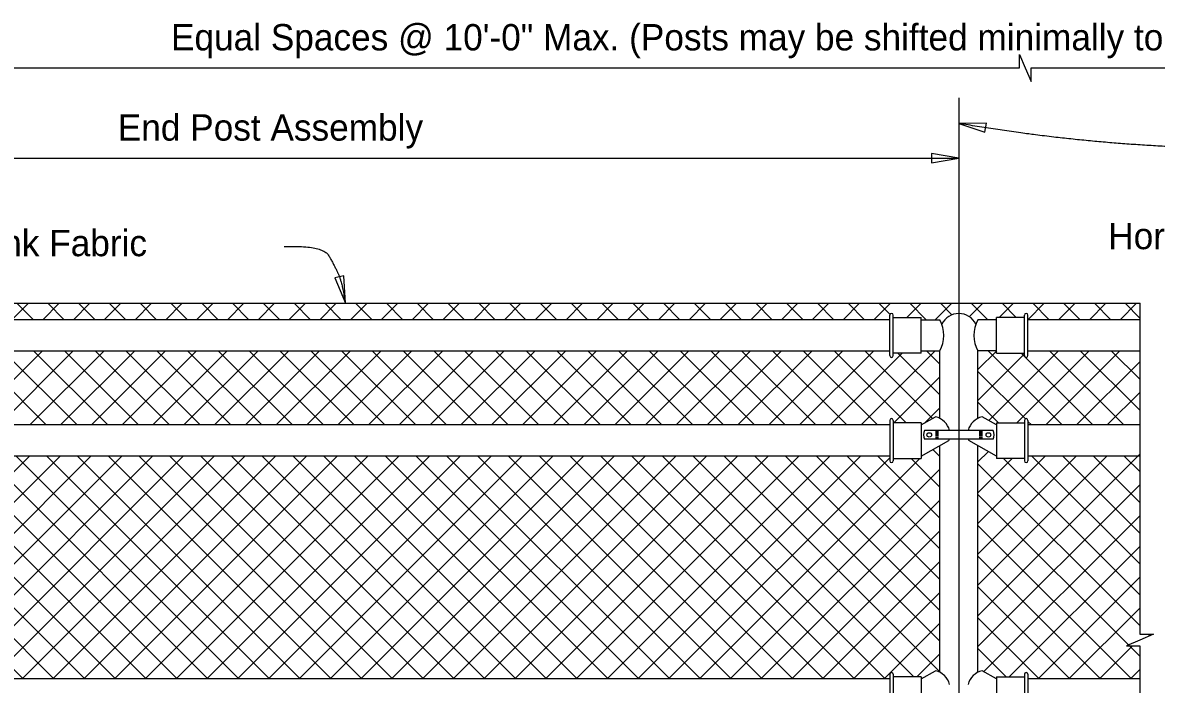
# Model space of a CAD drawing. Extents: x 110341.7 to 110413.5, y 110387.3 to 110417.8.
# Drawn here: x 110348.41 to 110357.09, y 110410.5 to 110415.57 of the extents above; entities that cross this region are included whole.
import ezdxf

# ---------------------------------------------------------------- set-up
doc = ezdxf.new("R2010")
doc.units = 0
for name, color, linetype in [('AdhocPoint_dp', 7, 'Continuous'), ('Border', 7, 'Continuous'), ('CL_Major', 7, 'Continuous'), ('Patterning', 7, 'Continuous'), ('SheetBorder_dp', 7, 'Continuous')]:
    doc.layers.add(name, color=color, linetype=linetype)

msp = doc.modelspace()

# ---------------------------------------------------------------- linework, layer by layer
at = {"layer": 'AdhocPoint_dp'}
for p, q in [((110355.0484, 110413.022), (110355.0484, 110413.3316)), ((110355.0753, 110413.022), (110355.0753, 110413.3316)), ((110355.0753, 110413.3138), (110355.2882, 110413.3138)), ((110355.2882, 110413.0415), (110355.2882, 110413.3138)), ((110355.2882, 110413.0415), (110355.2882, 110413.3138)), ((110355.8673, 110413.0415), (110355.8673, 110413.3138)), ((110356.0803, 110413.3138), (110355.8673, 110413.3138)), ((110356.0803, 110413.022), (110356.0803, 110413.3316)), ((110356.1071, 110413.022), (110356.1071, 110413.3316)), ((110355.0484, 110413.2966), (110346.1071, 110413.2966)), ((110355.2882, 110413.2957), (110355.4319, 110413.2957)), ((110355.8674, 110413.2957), (110355.7237, 110413.2957)), ((110356.9647, 110413.2966), (110356.1071, 110413.2966)), ((110355.0484, 110413.057), (110346.1071, 110413.057)), ((110355.2882, 110413.0415), (110355.0753, 110413.0415)), ((110355.2882, 110413.058), (110355.4319, 110413.058)), ((110355.432, 110412.5414), (110355.432, 110413.058)), ((110355.7237, 110412.5414), (110355.7237, 110413.058)), ((110355.8674, 110413.058), (110355.7237, 110413.058)), ((110355.8673, 110413.0415), (110356.0803, 110413.0415)), ((110356.9647, 110413.057), (110356.1071, 110413.057)), ((110355.0484, 110412.5261), (110355.0484, 110412.2165)), ((110355.0753, 110412.5261), (110355.0753, 110412.2165)), ((110355.2882, 110412.4919), (110355.3991, 110412.5532)), ((110355.8673, 110412.4919), (110355.7565, 110412.5532)), ((110356.0803, 110412.5261), (110356.0803, 110412.2165)), ((110356.1071, 110412.5261), (110356.1071, 110412.2165)), ((110355.0484, 110412.4912), (110346.1071, 110412.4912)), ((110355.2882, 110412.5066), (110355.0753, 110412.5066)), ((110355.2882, 110412.5066), (110355.2882, 110412.2344)), ((110355.8402, 110412.4493), (110355.3154, 110412.4493)), ((110355.3978, 110412.4415), (110355.4212, 110412.4415)), ((110355.3978, 110412.4319), (110355.4212, 110412.4319)), ((110355.7578, 110412.4415), (110355.7343, 110412.4415)), ((110355.7578, 110412.4319), (110355.7343, 110412.4319)), ((110355.8673, 110412.5066), (110355.8673, 110412.2344)), ((110355.8673, 110412.5066), (110356.0803, 110412.5066)), ((110356.9647, 110412.4912), (110356.1071, 110412.4912)), ((110355.2882, 110412.2525), (110355.5022, 110412.371)), ((110355.8402, 110412.3815), (110355.3154, 110412.3815)), ((110355.3978, 110412.421), (110355.4212, 110412.421)), ((110355.3978, 110412.4093), (110355.4212, 110412.4093)), ((110355.3978, 110412.3975), (110355.4212, 110412.3975)), ((110355.3978, 110412.3877), (110355.4212, 110412.3877)), ((110355.8673, 110412.2525), (110355.6534, 110412.371)), ((110355.7578, 110412.421), (110355.7343, 110412.421)), ((110355.7578, 110412.4093), (110355.7343, 110412.4093)), ((110355.7578, 110412.3975), (110355.7343, 110412.3975)), ((110355.7578, 110412.3877), (110355.7343, 110412.3877)), ((110355.432, 110410.5968), (110355.432, 110412.3322)), ((110355.7237, 110410.5969), (110355.7237, 110412.3321)), ((110355.0484, 110412.2516), (110346.1071, 110412.2516)), ((110355.0753, 110412.2344), (110355.2882, 110412.2344)), ((110356.0803, 110412.2344), (110355.8673, 110412.2344)), ((110356.9647, 110412.2516), (110356.1071, 110412.2516)), ((110355.2882, 110410.5473), (110355.3991, 110410.6087)), ((110355.8673, 110410.5473), (110355.7565, 110410.6087)), ((110355.0484, 110410.5466), (110346.1071, 110410.5466)), ((110355.0484, 110410.5816), (110355.0484, 110410.272)), ((110355.0753, 110410.5816), (110355.0753, 110410.272)), ((110355.2882, 110410.5621), (110355.0753, 110410.5621)), ((110355.2882, 110410.5621), (110355.2882, 110410.2898)), ((110355.8673, 110410.5621), (110355.8673, 110410.2898)), ((110355.8673, 110410.5621), (110356.0803, 110410.5621)), ((110356.0803, 110410.5816), (110356.0803, 110410.272)), ((110356.1071, 110410.5816), (110356.1071, 110410.272)), ((110356.9647, 110410.5466), (110356.1071, 110410.5466))]:
    msp.add_line(p, q, dxfattribs=at)
for centre, radius, start, end in [((110355.062, 110413.332), 0.0134, 0, 180), ((110355.5778, 110413.1987), 0.1459, 26.24953, 153.75047), ((110356.0936, 110413.332), 0.0134, 0, 180), ((110355.2183, 110413.1768), 0.2445, 330.92084, 29.07916), ((110355.9373, 110413.1768), 0.2445, 150.92084, 209.07916), ((110355.062, 110413.0222), 0.0134, 180, 0), ((110356.0936, 110413.0222), 0.0134, 180, 0), ((110355.062, 110412.5261), 0.0134, 0, 180), ((110356.0936, 110412.5261), 0.0134, 0, 180), ((110355.062, 110412.2163), 0.0134, 180, 0), ((110356.0936, 110412.2163), 0.0134, 180, 0), ((110355.062, 110410.5815), 0.0134, 0, 180), ((110356.0936, 110410.5815), 0.0134, 0, 180)]:
    msp.add_arc(centre, radius, start, end, dxfattribs=at)
for centre, major_axis, start_param, end_param in [((110355.3646, 110412.4173), (0.146, 0), 0.231126, 1.331255), ((110355.791, 110412.4173), (-0.146, 0), 4.95193, 6.05206), ((110355.3846, 110412.4153), (-0.0776, 0), 5.810211, 6.75616), ((110355.771, 110412.4153), (0.0776, 0), 5.810211, 6.75616), ((110355.3646, 110412.4173), (0.146, 0), 5.947976, 6.024627), ((110355.791, 110412.4173), (-0.146, 0), 0.258558, 0.335209), ((110355.3646, 110410.4727), (0.146, 0), 0.231126, 1.331255), ((110355.791, 110410.4727), (-0.146, 0), 4.95193, 6.05206)]:
    msp.add_ellipse(centre, major_axis=major_axis, ratio=0.957868, start_param=start_param, end_param=end_param, dxfattribs=at)
for centre, major_axis in [((110355.3512, 110412.4148), (0.0178, 0)), ((110355.8044, 110412.4148), (-0.0178, 0))]:
    msp.add_ellipse(centre, major_axis=major_axis, ratio=0.957868, dxfattribs=at)
at = {"layer": 'Border'}
for p, q in [((110343.2819, 110415.2246), (110354.5778, 110415.2246)), ((110345.5778, 110414.5336), (110355.5778, 110414.5336))]:
    msp.add_line(p, q, dxfattribs=at)
for points in [[(110354.5778, 110415.2246), (110356.0414, 110415.2246), (110356.0414, 110415.3279), (110356.0864, 110415.2246), (110356.1314, 110415.1213), (110356.1314, 110415.2246), (110367.5259, 110415.2246)], [(110356.9647, 110413.4227), (110356.9647, 110410.8892), (110357.0681, 110410.8892), (110356.9647, 110410.8442), (110356.8614, 110410.7992), (110356.9647, 110410.7992), (110356.9647, 110410.307)]]:
    msp.add_lwpolyline(points, dxfattribs=at)
for points in [[(110355.5778, 110414.8004), (110355.7778, 110414.7325), (110355.789, 110414.8021)], [(110355.5778, 110414.5336), (110355.3695, 110414.5689), (110355.3695, 110414.4983)], [(110350.8806, 110413.4227), (110350.8677, 110413.6335), (110350.799, 110413.6175)]]:
    msp.add_lwpolyline(points, close=True, dxfattribs=at)
for points in [[(110359.5594, 110414.6017), (110358.756, 110414.6017), (110357.3667, 110414.6017), (110356.1853, 110414.6963), (110355.5778, 110414.8004)], [(110350.4116, 110413.8578), (110350.709, 110413.867), (110350.7987, 110413.7074), (110350.8546, 110413.5877), (110350.8807, 110413.4227)]]:
    msp.add_open_spline(points, degree=2, dxfattribs=at)
at = {"layer": 'CL_Major'}
msp.add_line((110355.5778, 110414.9959), (110355.5778, 110405.5769), dxfattribs=at)
at = {"layer": 'Patterning'}
for p, q in [((110345.5778, 110413.4227), (110356.9648, 110413.4227)), ((110348.3275, 110413.2966), (110348.4536, 110413.4227)), ((110348.3663, 110413.4227), (110348.4924, 110413.2966)), ((110348.5632, 110413.2966), (110348.6893, 110413.4227)), ((110348.602, 110413.4227), (110348.7281, 110413.2966)), ((110348.7989, 110413.2966), (110348.925, 110413.4227)), ((110348.8377, 110413.4227), (110348.9638, 110413.2966)), ((110349.0346, 110413.2966), (110349.1607, 110413.4227)), ((110349.0734, 110413.4227), (110349.1995, 110413.2966)), ((110349.2703, 110413.2966), (110349.3964, 110413.4227)), ((110349.3091, 110413.4227), (110349.4352, 110413.2966)), ((110349.506, 110413.2966), (110349.6321, 110413.4227)), ((110349.5448, 110413.4227), (110349.6709, 110413.2966)), ((110349.7417, 110413.2966), (110349.8678, 110413.4227)), ((110349.7805, 110413.4227), (110349.9066, 110413.2966)), ((110349.9774, 110413.2966), (110350.1035, 110413.4227)), ((110350.0162, 110413.4227), (110350.1423, 110413.2966)), ((110350.2131, 110413.2966), (110350.3392, 110413.4227)), ((110350.2519, 110413.4227), (110350.378, 110413.2966)), ((110350.4488, 110413.2966), (110350.5749, 110413.4227)), ((110350.4876, 110413.4227), (110350.6137, 110413.2966)), ((110350.6845, 110413.2966), (110350.8106, 110413.4227)), ((110350.7233, 110413.4227), (110350.8494, 110413.2966)), ((110350.9202, 110413.2966), (110351.0463, 110413.4227)), ((110350.959, 110413.4227), (110351.0851, 110413.2966)), ((110351.1559, 110413.2966), (110351.282, 110413.4227)), ((110351.1947, 110413.4227), (110351.3208, 110413.2966)), ((110351.3916, 110413.2966), (110351.5177, 110413.4227)), ((110351.4304, 110413.4227), (110351.5565, 110413.2966)), ((110351.6273, 110413.2966), (110351.7534, 110413.4227)), ((110351.6661, 110413.4227), (110351.7922, 110413.2966)), ((110351.863, 110413.2966), (110351.9891, 110413.4227)), ((110351.9018, 110413.4227), (110352.0279, 110413.2966)), ((110352.0987, 110413.2966), (110352.2248, 110413.4227)), ((110352.1376, 110413.4227), (110352.2636, 110413.2966)), ((110352.3345, 110413.2966), (110352.4605, 110413.4227)), ((110352.3733, 110413.4227), (110352.4993, 110413.2966)), ((110352.5702, 110413.2966), (110352.6962, 110413.4227)), ((110352.609, 110413.4227), (110352.735, 110413.2966)), ((110352.8059, 110413.2966), (110352.9319, 110413.4227)), ((110352.8447, 110413.4227), (110352.9707, 110413.2966)), ((110353.0416, 110413.2966), (110353.1676, 110413.4227)), ((110353.0804, 110413.4227), (110353.2064, 110413.2966)), ((110353.2773, 110413.2966), (110353.4033, 110413.4227)), ((110353.3161, 110413.4227), (110353.4421, 110413.2966)), ((110353.513, 110413.2966), (110353.639, 110413.4227)), ((110353.5518, 110413.4227), (110353.6778, 110413.2966)), ((110353.7487, 110413.2966), (110353.8747, 110413.4227)), ((110353.7875, 110413.4227), (110353.9135, 110413.2966)), ((110353.9844, 110413.2966), (110354.1104, 110413.4227)), ((110354.0232, 110413.4227), (110354.1492, 110413.2966)), ((110354.2201, 110413.2966), (110354.3461, 110413.4227)), ((110354.2589, 110413.4227), (110354.3849, 110413.2966)), ((110354.4558, 110413.2966), (110354.5818, 110413.4227)), ((110354.4946, 110413.4227), (110354.6206, 110413.2966)), ((110354.6915, 110413.2966), (110354.8175, 110413.4227)), ((110354.7303, 110413.4227), (110354.8563, 110413.2966)), ((110354.9272, 110413.2966), (110355.0532, 110413.4227)), ((110354.966, 110413.4227), (110355.0502, 110413.3385)), ((110355.18, 110413.3138), (110355.2889, 110413.4227)), ((110355.2017, 110413.4227), (110355.3287, 110413.2957)), ((110355.3976, 110413.2957), (110355.5246, 110413.4227)), ((110355.4374, 110413.4227), (110355.5253, 110413.3348)), ((110355.6581, 110413.3205), (110355.7603, 110413.4227)), ((110355.6731, 110413.4227), (110355.8001, 110413.2957)), ((110355.8871, 110413.3138), (110355.996, 110413.4227)), ((110355.9088, 110413.4227), (110356.0177, 110413.3138)), ((110356.1057, 110413.2966), (110356.2317, 110413.4227)), ((110356.1445, 110413.4227), (110356.2705, 110413.2966)), ((110356.3414, 110413.2966), (110356.4674, 110413.4227)), ((110356.3802, 110413.4227), (110356.5062, 110413.2966)), ((110356.5771, 110413.2966), (110356.7031, 110413.4227)), ((110356.6159, 110413.4227), (110356.7419, 110413.2966)), ((110356.8128, 110413.2966), (110356.9388, 110413.4227)), ((110356.8516, 110413.4227), (110356.9647, 110413.3095)), ((110347.9935, 110412.4912), (110348.5593, 110413.057)), ((110348.0248, 110413.057), (110348.5907, 110412.4912)), ((110348.2292, 110412.4912), (110348.795, 110413.057)), ((110348.2605, 110413.057), (110348.8264, 110412.4912)), ((110348.4649, 110412.4912), (110349.0307, 110413.057)), ((110348.4962, 110413.057), (110349.0621, 110412.4912)), ((110348.7006, 110412.4912), (110349.2664, 110413.057)), ((110348.7319, 110413.057), (110349.2978, 110412.4912)), ((110348.9363, 110412.4912), (110349.5021, 110413.057)), ((110348.9677, 110413.057), (110349.5335, 110412.4912)), ((110349.172, 110412.4912), (110349.7378, 110413.057)), ((110349.2034, 110413.057), (110349.7692, 110412.4912)), ((110349.4077, 110412.4912), (110349.9735, 110413.057)), ((110349.4391, 110413.057), (110350.0049, 110412.4912)), ((110349.6434, 110412.4912), (110350.2093, 110413.057)), ((110349.6748, 110413.057), (110350.2406, 110412.4912)), ((110349.8791, 110412.4912), (110350.445, 110413.057)), ((110349.9105, 110413.057), (110350.4763, 110412.4912)), ((110350.1148, 110412.4912), (110350.6807, 110413.057)), ((110350.1462, 110413.057), (110350.712, 110412.4912)), ((110350.3505, 110412.4912), (110350.9164, 110413.057)), ((110350.3819, 110413.057), (110350.9477, 110412.4912)), ((110350.5862, 110412.4912), (110351.1521, 110413.057)), ((110350.6176, 110413.057), (110351.1834, 110412.4912)), ((110350.8219, 110412.4912), (110351.3878, 110413.057)), ((110350.8533, 110413.057), (110351.4191, 110412.4912)), ((110351.0576, 110412.4912), (110351.6235, 110413.057)), ((110351.089, 110413.057), (110351.6548, 110412.4912)), ((110351.2933, 110412.4912), (110351.8592, 110413.057)), ((110351.3247, 110413.057), (110351.8905, 110412.4912)), ((110351.529, 110412.4912), (110352.0949, 110413.057)), ((110351.5604, 110413.057), (110352.1262, 110412.4912)), ((110351.7647, 110412.4912), (110352.3306, 110413.057)), ((110351.7961, 110413.057), (110352.362, 110412.4912)), ((110352.0004, 110412.4912), (110352.5663, 110413.057)), ((110352.0318, 110413.057), (110352.5977, 110412.4912)), ((110352.2361, 110412.4912), (110352.802, 110413.057)), ((110352.2675, 110413.057), (110352.8334, 110412.4912)), ((110352.4718, 110412.4912), (110353.0377, 110413.057)), ((110352.5032, 110413.057), (110353.0691, 110412.4912)), ((110352.7075, 110412.4912), (110353.2734, 110413.057)), ((110352.7389, 110413.057), (110353.3048, 110412.4912)), ((110352.9432, 110412.4912), (110353.5091, 110413.057)), ((110352.9746, 110413.057), (110353.5405, 110412.4912)), ((110353.1789, 110412.4912), (110353.7448, 110413.057)), ((110353.2103, 110413.057), (110353.7762, 110412.4912)), ((110353.4146, 110412.4912), (110353.9805, 110413.057)), ((110353.446, 110413.057), (110354.0119, 110412.4912)), ((110353.6503, 110412.4912), (110354.2162, 110413.057)), ((110353.6817, 110413.057), (110354.2476, 110412.4912)), ((110353.886, 110412.4912), (110354.4519, 110413.057)), ((110353.9174, 110413.057), (110354.4833, 110412.4912)), ((110354.1217, 110412.4912), (110354.6876, 110413.057)), ((110354.1531, 110413.057), (110354.719, 110412.4912)), ((110354.3574, 110412.4912), (110354.9233, 110413.057)), ((110354.3888, 110413.057), (110354.9547, 110412.4912)), ((110354.5931, 110412.4912), (110355.1435, 110413.0415)), ((110354.6245, 110413.057), (110355.1749, 110412.5066)), ((110354.8288, 110412.4912), (110355.3957, 110413.058)), ((110354.8602, 110413.057), (110355.3765, 110412.5408)), ((110355.1114, 110413.0415), (110355.432, 110412.721)), ((110355.3307, 110413.058), (110355.432, 110412.9567)), ((110355.7237, 110412.9146), (110355.8674, 110413.0583)), ((110355.8021, 110413.058), (110356.3689, 110412.4912)), ((110355.8062, 110412.5258), (110356.3375, 110413.057)), ((110356.0228, 110412.5066), (110356.5732, 110413.057)), ((110356.0542, 110413.0415), (110356.6046, 110412.4912)), ((110356.243, 110412.4912), (110356.8089, 110413.057)), ((110356.2744, 110413.057), (110356.8403, 110412.4912)), ((110356.5101, 110413.057), (110356.9648, 110412.6024)), ((110356.7458, 110413.057), (110356.9648, 110412.8381)), ((110355.7237, 110412.6789), (110356.0803, 110413.0356)), ((110356.4787, 110412.4912), (110356.9648, 110412.9772)), ((110355.7237, 110412.9007), (110356.0868, 110412.5376)), ((110355.08, 110412.5066), (110355.432, 110412.8586)), ((110356.7144, 110412.4912), (110356.9648, 110412.7415)), ((110355.3167, 110412.5077), (110355.432, 110412.6229)), ((110355.7237, 110412.665), (110355.882, 110412.5066)), ((110356.1071, 110412.5172), (110356.1332, 110412.4912)), ((110355.3788, 110412.3027), (110355.432, 110412.2496)), ((110355.7237, 110412.2075), (110355.8039, 110412.2877)), ((110355.7237, 110411.029), (110356.9648, 110412.2701)), ((110346.709, 110412.2516), (110348.4139, 110410.5466)), ((110346.756, 110410.5466), (110348.461, 110412.2516)), ((110346.9447, 110412.2516), (110348.6496, 110410.5466)), ((110346.9917, 110410.5466), (110348.6967, 110412.2516)), ((110347.1804, 110412.2516), (110348.8853, 110410.5466)), ((110347.2274, 110410.5466), (110348.9324, 110412.2516)), ((110347.4161, 110412.2516), (110349.121, 110410.5466)), ((110347.4631, 110410.5466), (110349.1681, 110412.2516)), ((110347.6518, 110412.2516), (110349.3567, 110410.5466)), ((110347.6988, 110410.5466), (110349.4038, 110412.2516)), ((110347.8875, 110412.2516), (110349.5925, 110410.5466)), ((110347.9345, 110410.5466), (110349.6395, 110412.2516)), ((110348.1232, 110412.2516), (110349.8282, 110410.5466)), ((110348.1702, 110410.5466), (110349.8752, 110412.2516)), ((110348.3589, 110412.2516), (110350.0639, 110410.5466)), ((110348.4059, 110410.5466), (110350.1109, 110412.2516)), ((110348.5946, 110412.2516), (110350.2996, 110410.5466)), ((110348.6416, 110410.5466), (110350.3466, 110412.2516)), ((110348.8303, 110412.2516), (110350.5353, 110410.5466)), ((110348.8773, 110410.5466), (110350.5823, 110412.2516)), ((110349.066, 110412.2516), (110350.771, 110410.5466)), ((110349.113, 110410.5466), (110350.818, 110412.2516)), ((110349.3017, 110412.2516), (110351.0067, 110410.5466)), ((110349.3487, 110410.5466), (110351.0537, 110412.2516)), ((110349.5374, 110412.2516), (110351.2424, 110410.5466)), ((110349.5845, 110410.5466), (110351.2894, 110412.2516)), ((110349.7731, 110412.2516), (110351.4781, 110410.5466)), ((110349.8202, 110410.5466), (110351.5251, 110412.2516)), ((110350.0088, 110412.2516), (110351.7138, 110410.5466)), ((110350.0559, 110410.5466), (110351.7608, 110412.2516)), ((110350.2445, 110412.2516), (110351.9495, 110410.5466)), ((110350.2916, 110410.5466), (110351.9965, 110412.2516)), ((110350.4802, 110412.2516), (110352.1852, 110410.5466)), ((110350.5273, 110410.5466), (110352.2322, 110412.2516)), ((110350.7159, 110412.2516), (110352.4209, 110410.5466)), ((110350.763, 110410.5466), (110352.4679, 110412.2516)), ((110350.9516, 110412.2516), (110352.6566, 110410.5466)), ((110350.9987, 110410.5466), (110352.7036, 110412.2516)), ((110351.1873, 110412.2516), (110352.8923, 110410.5466)), ((110351.2344, 110410.5466), (110352.9393, 110412.2516)), ((110351.423, 110412.2516), (110353.128, 110410.5466)), ((110351.4701, 110410.5466), (110353.175, 110412.2516)), ((110351.6587, 110412.2516), (110353.3637, 110410.5466)), ((110351.7058, 110410.5466), (110353.4107, 110412.2516)), ((110351.8944, 110412.2516), (110353.5994, 110410.5466)), ((110351.9415, 110410.5466), (110353.6464, 110412.2516)), ((110352.1301, 110412.2516), (110353.8351, 110410.5466)), ((110352.1772, 110410.5466), (110353.8821, 110412.2516)), ((110352.3658, 110412.2516), (110354.0708, 110410.5466)), ((110352.4129, 110410.5466), (110354.1178, 110412.2516)), ((110352.6015, 110412.2516), (110354.3065, 110410.5466)), ((110352.6486, 110410.5466), (110354.3535, 110412.2516)), ((110352.8372, 110412.2516), (110354.5422, 110410.5466)), ((110352.8843, 110410.5466), (110354.5892, 110412.2516)), ((110353.0729, 110412.2516), (110354.7779, 110410.5466)), ((110353.12, 110410.5466), (110354.8249, 110412.2516)), ((110353.3086, 110412.2516), (110355.0136, 110410.5466)), ((110353.3557, 110410.5466), (110355.0484, 110412.2394)), ((110353.5443, 110412.2516), (110355.2338, 110410.5621)), ((110353.5914, 110410.5466), (110355.2792, 110412.2344)), ((110353.78, 110412.2516), (110355.432, 110410.5996)), ((110354.0157, 110412.2516), (110355.432, 110410.8353)), ((110354.2515, 110412.2516), (110355.432, 110411.071)), ((110354.4872, 110412.2516), (110355.432, 110411.3067)), ((110354.7229, 110412.2516), (110355.432, 110411.5424)), ((110354.9586, 110412.2516), (110355.432, 110411.7782)), ((110355.2114, 110412.2344), (110355.432, 110412.0139)), ((110355.7237, 110411.2647), (110356.7106, 110412.2516)), ((110355.7237, 110411.5004), (110356.4749, 110412.2516)), ((110355.7237, 110411.7361), (110356.2392, 110412.2516)), ((110355.7237, 110411.9718), (110355.9863, 110412.2344)), ((110355.7237, 110412.1936), (110356.9648, 110410.9525)), ((110355.9186, 110412.2344), (110356.9648, 110411.1882)), ((110356.1371, 110412.2516), (110356.9648, 110411.4239)), ((110356.3728, 110412.2516), (110356.9648, 110411.6596)), ((110356.6085, 110412.2516), (110356.9648, 110411.8953)), ((110356.8442, 110412.2516), (110356.9648, 110412.131)), ((110353.8271, 110410.5466), (110355.432, 110412.1515)), ((110355.7237, 110410.7933), (110356.9648, 110412.0344)), ((110354.0628, 110410.5466), (110355.432, 110411.9158)), ((110355.7237, 110411.9579), (110356.9648, 110410.7168)), ((110355.7683, 110410.6022), (110356.9648, 110411.7987)), ((110354.2985, 110410.5466), (110355.432, 110411.6801)), ((110355.7237, 110411.7222), (110356.8992, 110410.5466)), ((110355.7237, 110411.4865), (110356.6635, 110410.5466)), ((110355.9639, 110410.5621), (110356.9648, 110411.563)), ((110354.5342, 110410.5466), (110355.432, 110411.4444)), ((110356.1841, 110410.5466), (110356.9648, 110411.3273)), ((110355.7237, 110411.2508), (110356.4278, 110410.5466)), ((110354.7699, 110410.5466), (110355.432, 110411.2087)), ((110356.4198, 110410.5466), (110356.9648, 110411.0916)), ((110355.0056, 110410.5466), (110355.432, 110410.973)), ((110355.7237, 110411.0151), (110356.1921, 110410.5466)), ((110357.028, 110410.8892), (110357.0402, 110410.8771)), ((110356.6555, 110410.5466), (110356.9081, 110410.7992)), ((110355.2568, 110410.5621), (110355.432, 110410.7373)), ((110355.7237, 110410.7794), (110355.9409, 110410.5621)), ((110349.8202, 110410.5466), (110349.9406, 110410.6671)), ((110356.8912, 110410.5466), (110356.9648, 110410.6202))]:
    msp.add_line(p, q, dxfattribs=at)

# ---------------------------------------------------------------- texts
at = {"layer": 'SheetBorder_dp'}
for s, p in [('Equal Spaces @ 10\'-0" Max. (Posts may be shifted minimally to meet required clearances)', (110349.5454, 110415.3593)), ('End Post Assembly', (110349.1382, 110414.6683)), ('Top of Chain Link Fabric', (110346.425, 110413.7833)), ('Horizontal Rails', (110356.7217, 110413.837))]:
    msp.add_text(s, height=0.2016, dxfattribs=at).set_placement(p)

doc.saveas('drawing.dxf')
